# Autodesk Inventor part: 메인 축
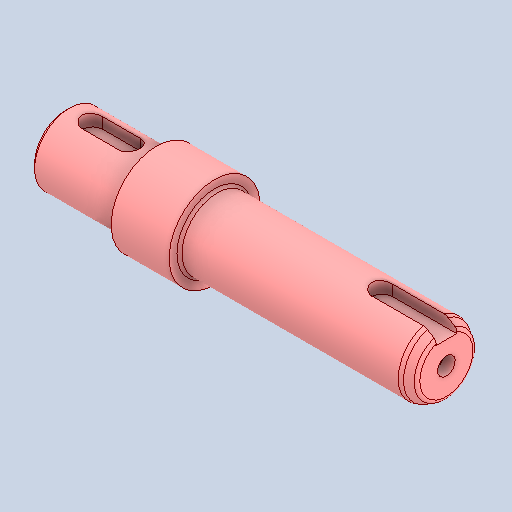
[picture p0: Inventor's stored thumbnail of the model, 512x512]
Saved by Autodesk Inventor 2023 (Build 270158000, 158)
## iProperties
Created: 2025-04
Part Number: 메인 축
Material: 강철, 탄소
Document SubType Name: Modeling
Designer: Admin
Density: 7.85 g/cm^3
Appearance: 기본값
Author: jhkim
Sending System: Autodesk Inventor 2026
Preprocessor: ST-DEVELOPER v20.1
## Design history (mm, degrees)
feature "솔리드1"
node "솔리드2"
